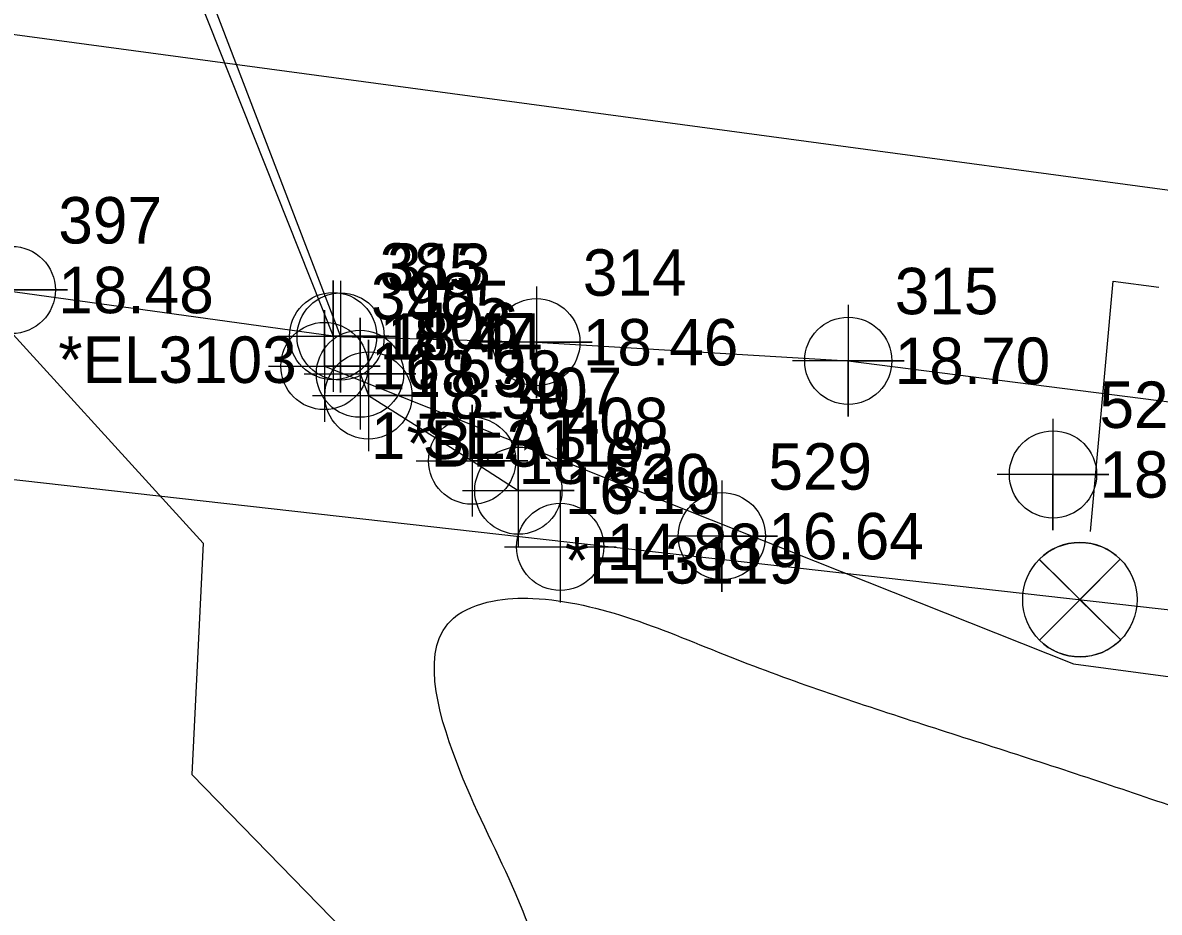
# Model space of a CAD drawing. Extents: x 2627243 to 2636458, y 566398 to 571062.
# Drawn here: x 2634660.8 to 2634722, y 569047.1 to 569095 of the extents above; entities that cross this region are included whole.
import ezdxf

# ---------------------------------------------------------------- set-up
doc = ezdxf.new("R2010")
doc.units = 0
for name, color, linetype in [('COGO Default Chain', 7, 'Continuous'), ('Cogo Default Point CELL', 7, 'Continuous'), ('COGO Default Point Elevation', 7, 'Continuous'), ('COGO Default Point Number', 7, 'Continuous'), ('Exist Horizontal Alignment', 7, 'Continuous'), ('Exist Hydro Jurisdictional Stream or Body of Water', 7, 'Continuous'), ('Exist Roads EOP', 7, 'Continuous'), ('Exist Roads EOP Cogo Elevation', 7, 'Continuous'), ('Exist Roads EOP Cogo Number', 7, 'Continuous'), ('Exist Roads EOP Cogo Point CELL', 7, 'Continuous'), ('Exist Structure Major Bridge Seam Cogo Comment', 7, 'Continuous'), ('Exist Structure Major Bridge Seam Cogo Elevation', 7, 'Continuous'), ('Exist Structure Major Bridge Seam Cogo Number', 7, 'Continuous'), ('Exist Structure Major Bridge Seam Cogo Point CELL', 7, 'Continuous'), ('Exist Structure Major Bridge Seat Cogo Comment', 7, 'Continuous'), ('Exist Structure Major Bridge Seat Cogo Elevation', 7, 'Continuous'), ('Exist Structure Major Bridge Seat Cogo Number', 7, 'Continuous'), ('Exist Structure Major Bridge Seat Cogo Point CELL', 7, 'Continuous'), ('Exist Structure Major Bridge Seat Top Elevation', 7, 'Continuous'), ('Exist Structure Major Bridge WW', 7, 'Continuous'), ('Exist Structure Major Bridge WW Cogo Comment', 7, 'Continuous'), ('Exist Structure Major Bridge WW Cogo Elevation', 7, 'Continuous'), ('Exist Structure Major Bridge WW Cogo Number', 7, 'Continuous'), ('Exist Structure Major Bridge WW Cogo Point CELL', 7, 'Continuous'), ('Exist Structure Major Deck Tunnel Box Culvert', 7, 'Continuous'), ('Exist Structure Major Deck Tunnel Box Culvert Cogo Elevation', 7, 'Continuous'), ('Exist Structure Major Deck Tunnel Box Culvert Cogo Number', 7, 'Continuous'), ('Exist Structure Major Deck Tunnel Box Culvert Cogo Point CELL', 7, 'Continuous'), ('Exist Utilities Water Test Hole SUE CELL', 7, 'Continuous'), ('Exist Utilities Water Test Hole SUE Leader', 7, 'Continuous'), ('Exist Utilities Water UG Line', 7, 'Continuous'), ('Exist Utilities Water UG Line Cogo Elevation', 7, 'Continuous'), ('Exist Utilities Water UG Line Cogo Number', 7, 'Continuous'), ('Exist Utilities Water UG Line Cogo Point CELL', 7, 'Continuous'), ('Exist Vegetation Woods Line', 7, 'Continuous')]:
    doc.layers.add(name, color=color, linetype=linetype)

# ---------------------------------------------------------------- blocks, each defined once
blk = doc.blocks.new('EXIST ROADS EOP COGO POINT')
at = {"layer": 'Exist Roads EOP Cogo Point CELL'}
blk.add_lwpolyline([(0, 0.06), (0, -0.06), (0, 0), (0.06, 0), (-0.06, 0)], dxfattribs=at)
blk.add_circle((0, 0), 0.0469, dxfattribs=at)
blk = doc.blocks.new('EXIST STRUCTURE MAJOR DECK TUNNEL BOX CULVERT COGO POINT')
at = {"layer": 'Exist Structure Major Deck Tunnel Box Culvert Cogo Point CELL'}
blk.add_lwpolyline([(-0.06, 0), (0.06, 0), (0, 0), (0, 0.06), (0, -0.06)], dxfattribs=at)
blk.add_circle((0, 0), 0.0469, dxfattribs=at)
blk = doc.blocks.new('EXIST BRIDGE SEAM COGO POINT')
at = {"layer": 'Exist Structure Major Bridge Seam Cogo Point CELL'}
blk.add_lwpolyline([(0, 0.06), (0, -0.06), (0, 0), (0.06, 0), (-0.06, 0)], dxfattribs=at)
blk.add_circle((0, 0), 0.0469, dxfattribs=at)
blk = doc.blocks.new('EXIST STRUCTURE MAJOR BRIDGE SEAT COGO POINT')
at = {"layer": 'Exist Structure Major Bridge Seat Cogo Point CELL'}
blk.add_lwpolyline([(-0.06, 0), (0.06, 0), (0, 0), (0, 0.06), (0, -0.06)], dxfattribs=at)
blk.add_circle((0, 0), 0.0469, dxfattribs=at)
blk = doc.blocks.new('EXIST STRUCTURE MAJOR BRIDGE WW COGO POINT')
at = {"layer": 'Exist Structure Major Bridge WW Cogo Point CELL'}
blk.add_lwpolyline([(-0.06, 0), (0.06, 0), (0, 0), (0, 0.06), (0, -0.06)], dxfattribs=at)
blk.add_circle((0, 0), 0.0469, dxfattribs=at)
blk = doc.blocks.new('EXIST UTILITIES WATER UG LINE COGO POINT')
at = {"layer": 'Exist Utilities Water UG Line Cogo Point CELL'}
blk.add_lwpolyline([(0, 0.06), (0, -0.06), (0, 0), (0.06, 0), (-0.06, 0)], dxfattribs=at)
blk.add_circle((0, 0), 0.0469, dxfattribs=at)
blk = doc.blocks.new('COGO DEFAULT POINT')
at = {"layer": 'Cogo Default Point CELL'}
for points in [[(0, 0.06), (0, 0)], [(-0.06, 0), (0, 0)], [(0, 0), (0.06, 0)], [(0, 0), (0, -0.06)]]:
    blk.add_lwpolyline(points, dxfattribs=at)
blk.add_circle((0, 0), 0.0469, dxfattribs=at)

msp = doc.modelspace()

# ---------------------------------------------------------------- linework, layer by layer
at = {"layer": 'COGO Default Chain'}
msp.add_line((2634072.78, 569173.542), (2634872.745, 569065.698), dxfattribs=at)
msp.add_line((2634072.78, 569173.542), (2634872.745, 569065.698), dxfattribs=at)
at = {"layer": 'Exist Horizontal Alignment'}
msp.add_line((2634072.78, 569173.542), (2634872.745, 569065.698), dxfattribs=at)
at = {"layer": 'Exist Hydro Jurisdictional Stream or Body of Water'}
msp.add_lwpolyline([(2634657.905, 569080.815), (2634670.524, 569066.96), (2634669.908, 569054.527), (2634688.991, 569034.933)], dxfattribs=at)
at = {"layer": 'Exist Roads EOP'}
msp.add_lwpolyline([(2634756.154, 569092.132), (2634708.467, 569098.258), (2634691.47, 569100.768), (2634667.356, 569105.661), (2634677.917, 569078.08), (2634688.445, 569077.775), (2634705.225, 569076.779), (2634739.193, 569072.427), (2634781.279, 569066.947)], dxfattribs=at)
at = {"layer": 'Exist Structure Major Bridge Seat Top Elevation'}
msp.add_lwpolyline([(2634677.043, 569076.496), (2634717.336, 569060.479), (2634757.082, 569055.141)], dxfattribs=at)
at = {"layer": 'Exist Structure Major Bridge WW'}
msp.add_lwpolyline([(2634678.96, 569076.082), (2634679.409, 569074.91), (2634684.986, 569071.403), (2634687.476, 569069.791)], dxfattribs=at)
at = {"layer": 'Exist Structure Major Deck Tunnel Box Culvert'}
msp.add_lwpolyline([(2634565.456, 569119.889), (2634666.463, 569105.901), (2634677.512, 569078.102), (2634576.153, 569092.129), (2634565.524, 569119.463)], dxfattribs=at)
at = {"layer": 'Exist Utilities Water Test Hole SUE CELL'}
for points in [[(2634715.516, 569061.745), (2634719.86, 569066.102), (2634717.688, 569063.924), (2634719.862, 569061.787), (2634715.487, 569066.1)], [(2634715.497, 569066.09), (2634717.691, 569063.927), (2634717.691, 569063.927), (2634719.86, 569066.102), (2634719.86, 569066.102)], [(2634719.879, 569061.77), (2634719.862, 569061.787), (2634717.688, 569063.924), (2634715.516, 569061.745)]]:
    msp.add_lwpolyline(points, dxfattribs=at)
msp.add_circle((2634717.685, 569063.927), 3.077, dxfattribs=at)
for start, end in [(45, 135.3289), (225.16512, 315.49534)]:
    msp.add_arc((2634717.685, 569063.927), 3.077, start, end, dxfattribs=at)
at = {"layer": 'Exist Utilities Water Test Hole SUE Leader'}
msp.add_lwpolyline([(2634718.254, 569067.59), (2634719.471, 569081.067), (2634721.926, 569080.735)], dxfattribs=at)
at = {"layer": 'Exist Utilities Water UG Line'}
msp.add_lwpolyline([(2634491.938, 569094.669), (2634504.797, 569090.483), (2634523.376, 569085.838), (2634745.287, 569060.808)], dxfattribs=at)
at = {"layer": 'Exist Vegetation Woods Line'}
msp.add_spline([(2634648.605, 568711.487), (2634653.173, 568721.16), (2634653.751, 568723.17), (2634653.062, 568734.655), (2634652.681, 568736.88), (2634653.811, 568745.816), (2634654.682, 568748.012), (2634657.462, 568751.415), (2634662.006, 568762.101), (2634666.134, 568771.495), (2634670.477, 568781.848), (2634675.662, 568793.145), (2634680.221, 568804.456), (2634684.286, 568815.25), (2634687.607, 568827.217), (2634691.496, 568836.665), (2634694.841, 568847.62), (2634698.696, 568859.72), (2634702.614, 568870.42), (2634706.547, 568881.746), (2634708.602, 568893.118), (2634707.859, 568904.363), (2634707.859, 568914.434), (2634708.964, 568924.382), (2634711.312, 568935.939), (2634713.66, 568947.496), (2634714.717, 568959.47), (2634715.613, 568970.724), (2634714.708, 568981.25), (2634713.309, 568991.258), (2634709.845, 569001.605), (2634703.677, 569011.679), (2634697.548, 569021.366), (2634694.645, 569026.929), (2634691.128, 569037.035), (2634687.161, 569048.502), (2634684.142, 569055.224), (2634683.989, 569062.938), (2634686.083, 569063.851), (2634688.255, 569063.992), (2634698.877, 569060.848), (2634708.912, 569057.331), (2634719.002, 569054.055), (2634728.998, 569050.925), (2634740.663, 569049.057), (2634752.01, 569048.015), (2634763.876, 569046.479), (2634774.812, 569046.411), (2634786.684, 569047.139), (2634798.51, 569045.99), (2634811.388, 569044.478), (2634822.056, 569043.211), (2634833.271, 569042.703), (2634842.818, 569040.933), (2634849.22, 569038.612), (2634860.807, 569037.516), (2634873.074, 569036.645), (2634877.696, 569036.487), (2634881.962, 569037.542), (2634884.259, 569038.049)], degree=3, dxfattribs=at)

# ---------------------------------------------------------------- block references
at = {"layer": 'Cogo Default Point CELL', "xscale": 50, "yscale": 50}
msp.add_blockref('COGO DEFAULT POINT', (2634689.731, 569066.766), dxfattribs=at)
at = {"layer": 'Exist Roads EOP Cogo Point CELL', "xscale": 50, "yscale": 50}
for p in [(2634677.917, 569078.08), (2634688.445, 569077.775), (2634705.225, 569076.779)]:
    msp.add_blockref('EXIST ROADS EOP COGO POINT', p, dxfattribs=at)
at = {"layer": 'Exist Structure Major Bridge Seam Cogo Point CELL', "xscale": 50, "yscale": 50}
msp.add_blockref('EXIST BRIDGE SEAM COGO POINT', (2634660.229, 569080.586), dxfattribs=at)
at = {"layer": 'Exist Structure Major Bridge Seat Cogo Point CELL', "xscale": 50, "yscale": 50}
msp.add_blockref('EXIST STRUCTURE MAJOR BRIDGE SEAT COGO POINT', (2634677.043, 569076.496), dxfattribs=at)
at = {"layer": 'Exist Structure Major Bridge WW Cogo Point CELL', "xscale": 50, "yscale": 50}
for p in [(2634678.96, 569076.082), (2634679.409, 569074.91), (2634684.986, 569071.403), (2634687.476, 569069.791)]:
    msp.add_blockref('EXIST STRUCTURE MAJOR BRIDGE WW COGO POINT', p, dxfattribs=at)
at = {"layer": 'Exist Structure Major Deck Tunnel Box Culvert Cogo Point CELL', "xscale": 50, "yscale": 50}
msp.add_blockref('EXIST STRUCTURE MAJOR DECK TUNNEL BOX CULVERT COGO POINT', (2634677.512, 569078.102), dxfattribs=at)
at = {"layer": 'Exist Utilities Water UG Line Cogo Point CELL', "xscale": 50, "yscale": 50}
for p in [(2634716.237, 569070.663), (2634698.425, 569067.343)]:
    msp.add_blockref('EXIST UTILITIES WATER UG LINE COGO POINT', p, dxfattribs=at)

# ---------------------------------------------------------------- texts
at = {"layer": 'COGO Default Point Elevation'}
msp.add_text('14.88', height=2.5, dxfattribs=at).set_placement((2634692.231, 569065.516))
at = {"layer": 'COGO Default Point Number'}
msp.add_text('530', height=2.5, dxfattribs=at).set_placement((2634692.231, 569069.266))
at = {"layer": 'Exist Roads EOP Cogo Elevation'}
for s, p in [('18.44', (2634680.417, 569076.83)), ('18.46', (2634690.945, 569076.525)), ('18.70', (2634707.725, 569075.529))]:
    msp.add_text(s, height=2.5, dxfattribs=at).set_placement(p)
at = {"layer": 'Exist Roads EOP Cogo Number'}
for s, p in [('313', (2634680.417, 569080.58)), ('314', (2634690.945, 569080.275)), ('315', (2634707.725, 569079.279))]:
    msp.add_text(s, height=2.5, dxfattribs=at).set_placement(p)
at = {"layer": 'Exist Structure Major Bridge Seam Cogo Comment'}
msp.add_text('*EL3103', height=2.5, dxfattribs=at).set_placement((2634662.729, 569075.586))
at = {"layer": 'Exist Structure Major Bridge Seam Cogo Elevation'}
msp.add_text('18.48', height=2.5, dxfattribs=at).set_placement((2634662.729, 569079.336))
at = {"layer": 'Exist Structure Major Bridge Seam Cogo Number'}
msp.add_text('397', height=2.5, dxfattribs=at).set_placement((2634662.729, 569083.086))
at = {"layer": 'Exist Structure Major Bridge Seat Cogo Comment'}
msp.add_text('1 SEAT', height=2.5, dxfattribs=at).set_placement((2634679.543, 569071.496))
at = {"layer": 'Exist Structure Major Bridge Seat Cogo Elevation'}
msp.add_text('16.69', height=2.5, dxfattribs=at).set_placement((2634679.543, 569075.246))
at = {"layer": 'Exist Structure Major Bridge Seat Cogo Number'}
msp.add_text('398', height=2.5, dxfattribs=at).set_placement((2634679.543, 569078.996))
at = {"layer": 'Exist Structure Major Bridge WW Cogo Comment'}
for s, p in [('*BL3119', (2634681.46, 569071.082)), ('*EL3119', (2634689.976, 569064.791))]:
    msp.add_text(s, height=2.5, dxfattribs=at).set_placement(p)
at = {"layer": 'Exist Structure Major Bridge WW Cogo Elevation'}
for s, p in [('18.38', (2634681.46, 569074.832)), ('18.39', (2634681.909, 569073.66)), ('18.02', (2634687.486, 569070.153)), ('16.19', (2634689.976, 569068.541))]:
    msp.add_text(s, height=2.5, dxfattribs=at).set_placement(p)
at = {"layer": 'Exist Structure Major Bridge WW Cogo Number'}
for s, p in [('405', (2634681.46, 569078.582)), ('406', (2634681.909, 569077.41)), ('407', (2634687.486, 569073.903)), ('408', (2634689.976, 569072.291))]:
    msp.add_text(s, height=2.5, dxfattribs=at).set_placement(p)
at = {"layer": 'Exist Structure Major Deck Tunnel Box Culvert Cogo Elevation'}
msp.add_text('18.47', height=2.5, dxfattribs=at).set_placement((2634680.012, 569076.852))
at = {"layer": 'Exist Structure Major Deck Tunnel Box Culvert Cogo Number'}
msp.add_text('385', height=2.5, dxfattribs=at).set_placement((2634680.012, 569080.602))
at = {"layer": 'Exist Utilities Water UG Line Cogo Elevation'}
for s, p in [('18.01', (2634718.737, 569069.413)), ('16.64', (2634700.925, 569066.093))]:
    msp.add_text(s, height=2.5, dxfattribs=at).set_placement(p)
at = {"layer": 'Exist Utilities Water UG Line Cogo Number'}
for s, p in [('528', (2634718.737, 569073.163)), ('529', (2634700.925, 569069.843))]:
    msp.add_text(s, height=2.5, dxfattribs=at).set_placement(p)

doc.saveas('drawing.dxf')
